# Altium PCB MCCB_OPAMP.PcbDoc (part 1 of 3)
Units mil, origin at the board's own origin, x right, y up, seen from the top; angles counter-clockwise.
Board outline 3937.01 x 3937.01 mil, 2 copper layers (Top Layer, Bottom Layer), stack 62 mil thick; 238 components, 115 nets, 518 pads, 159 vias.
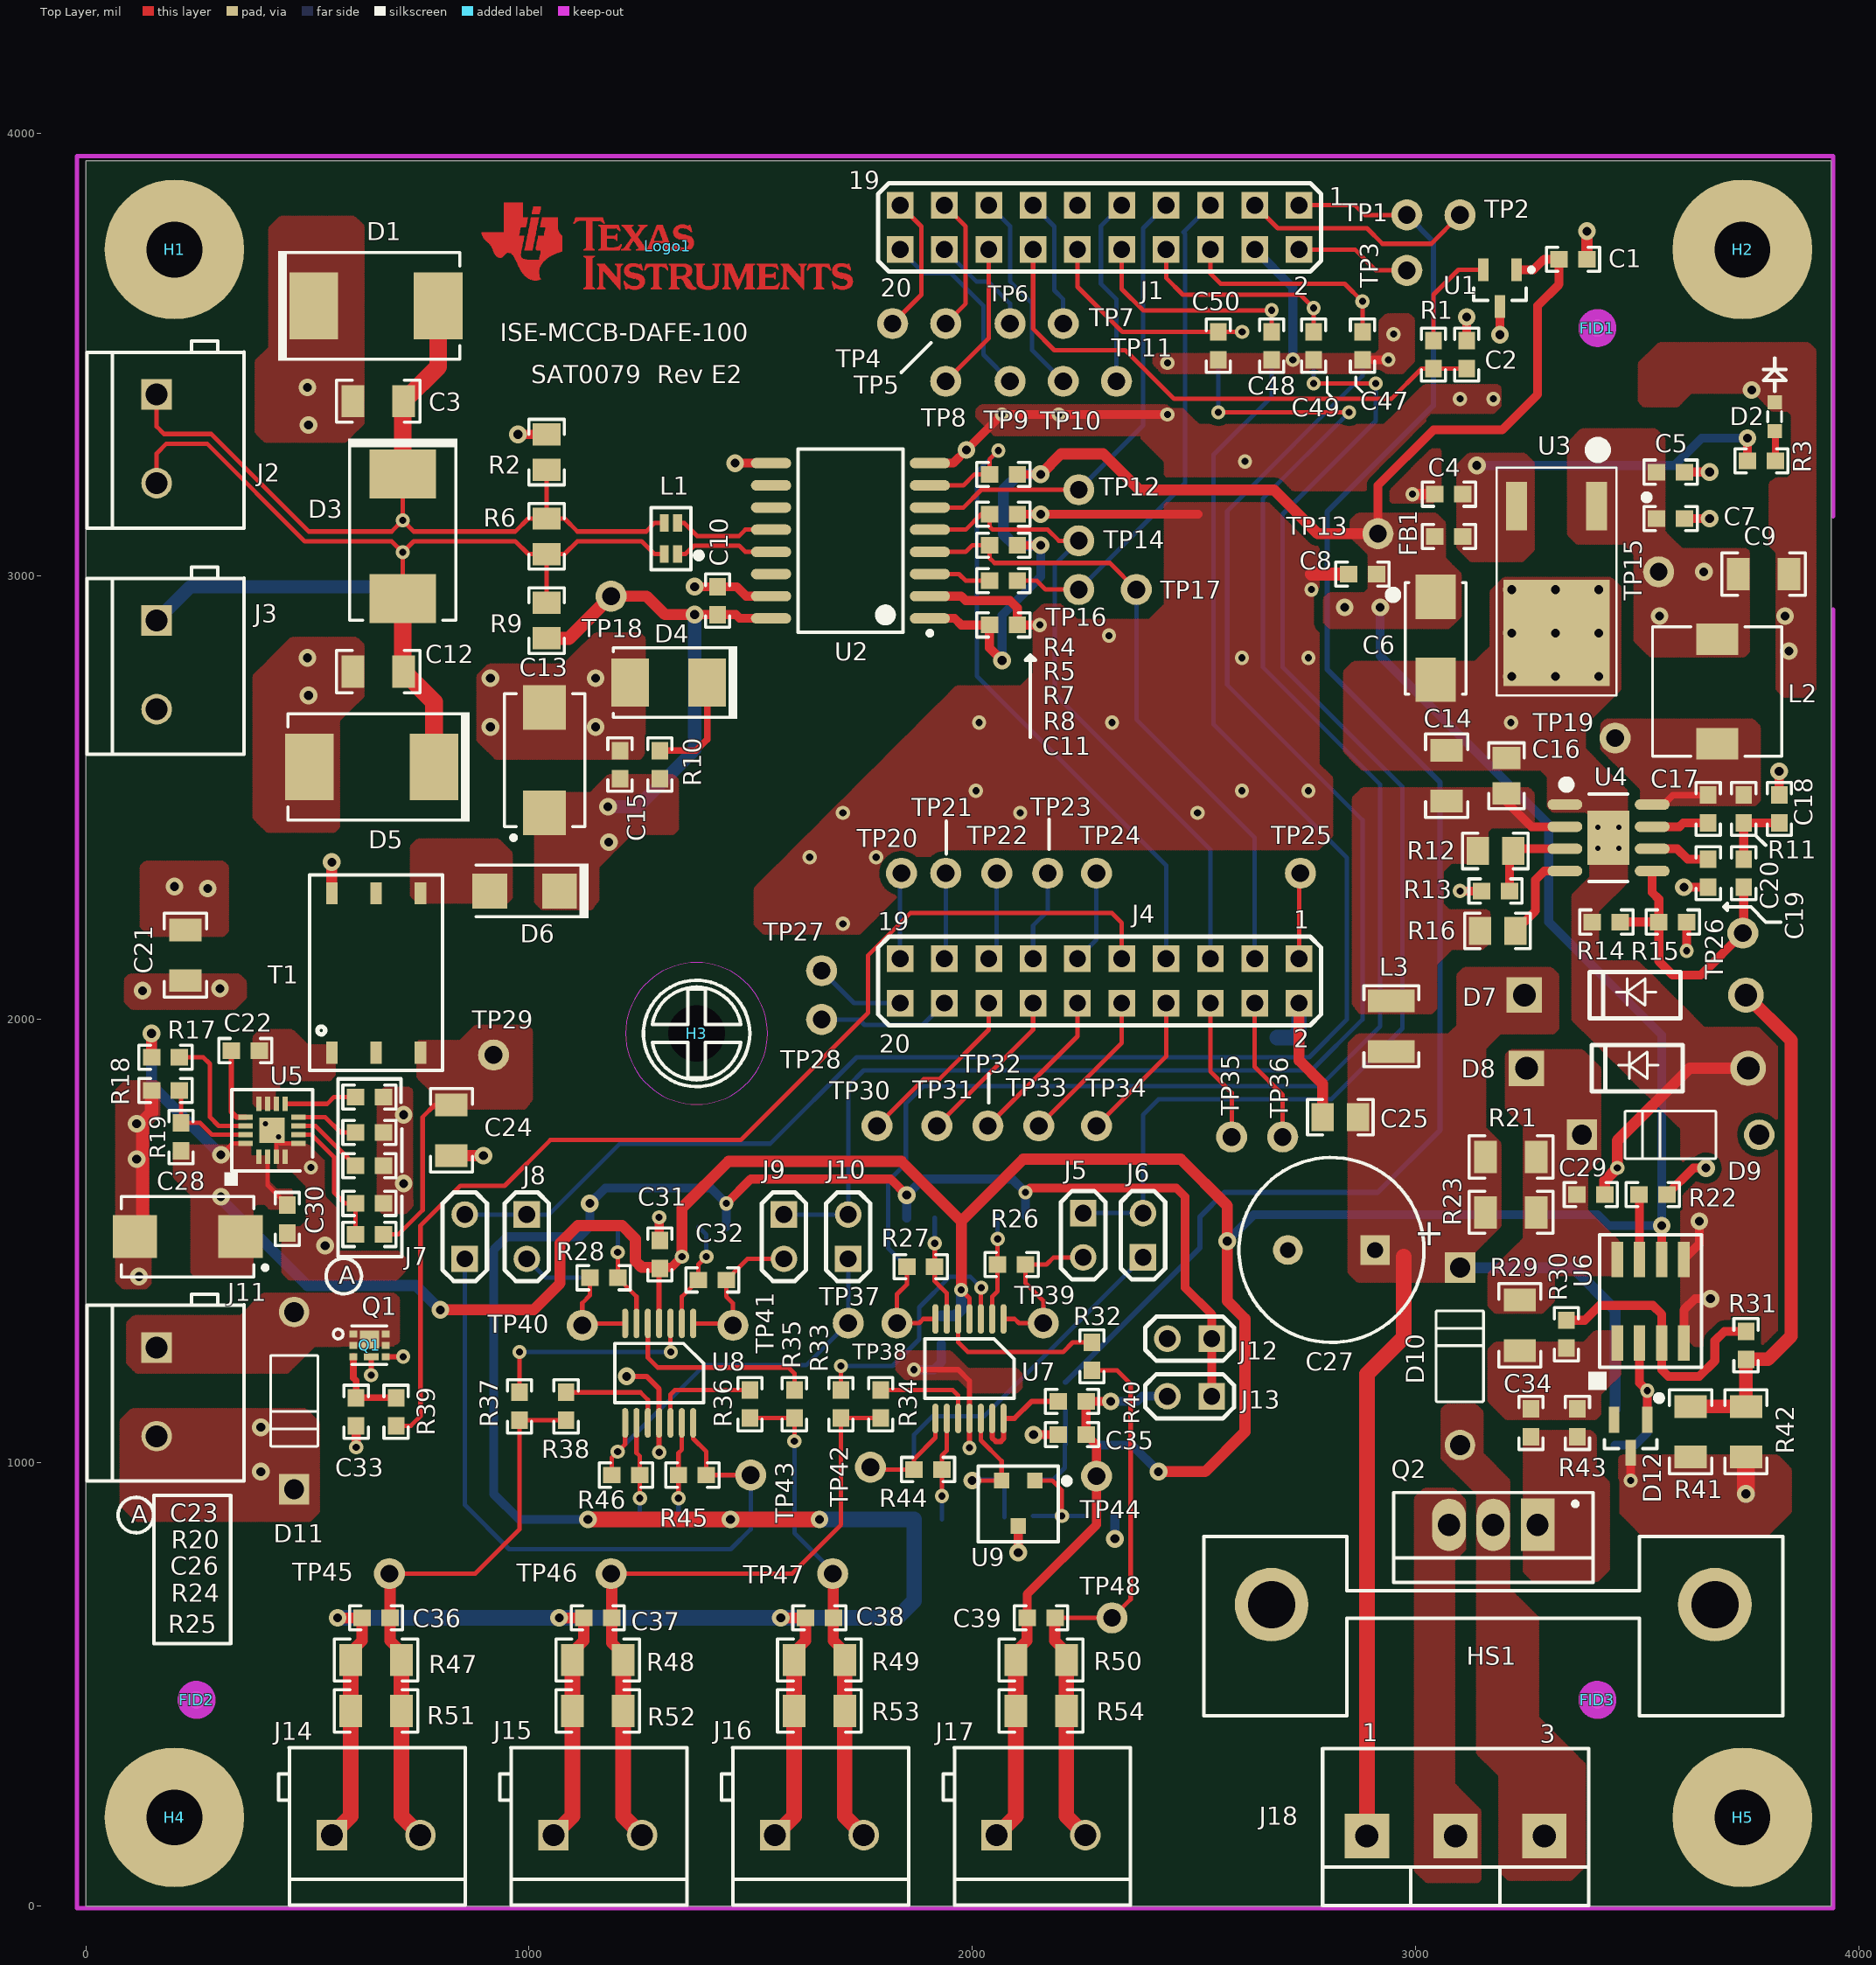
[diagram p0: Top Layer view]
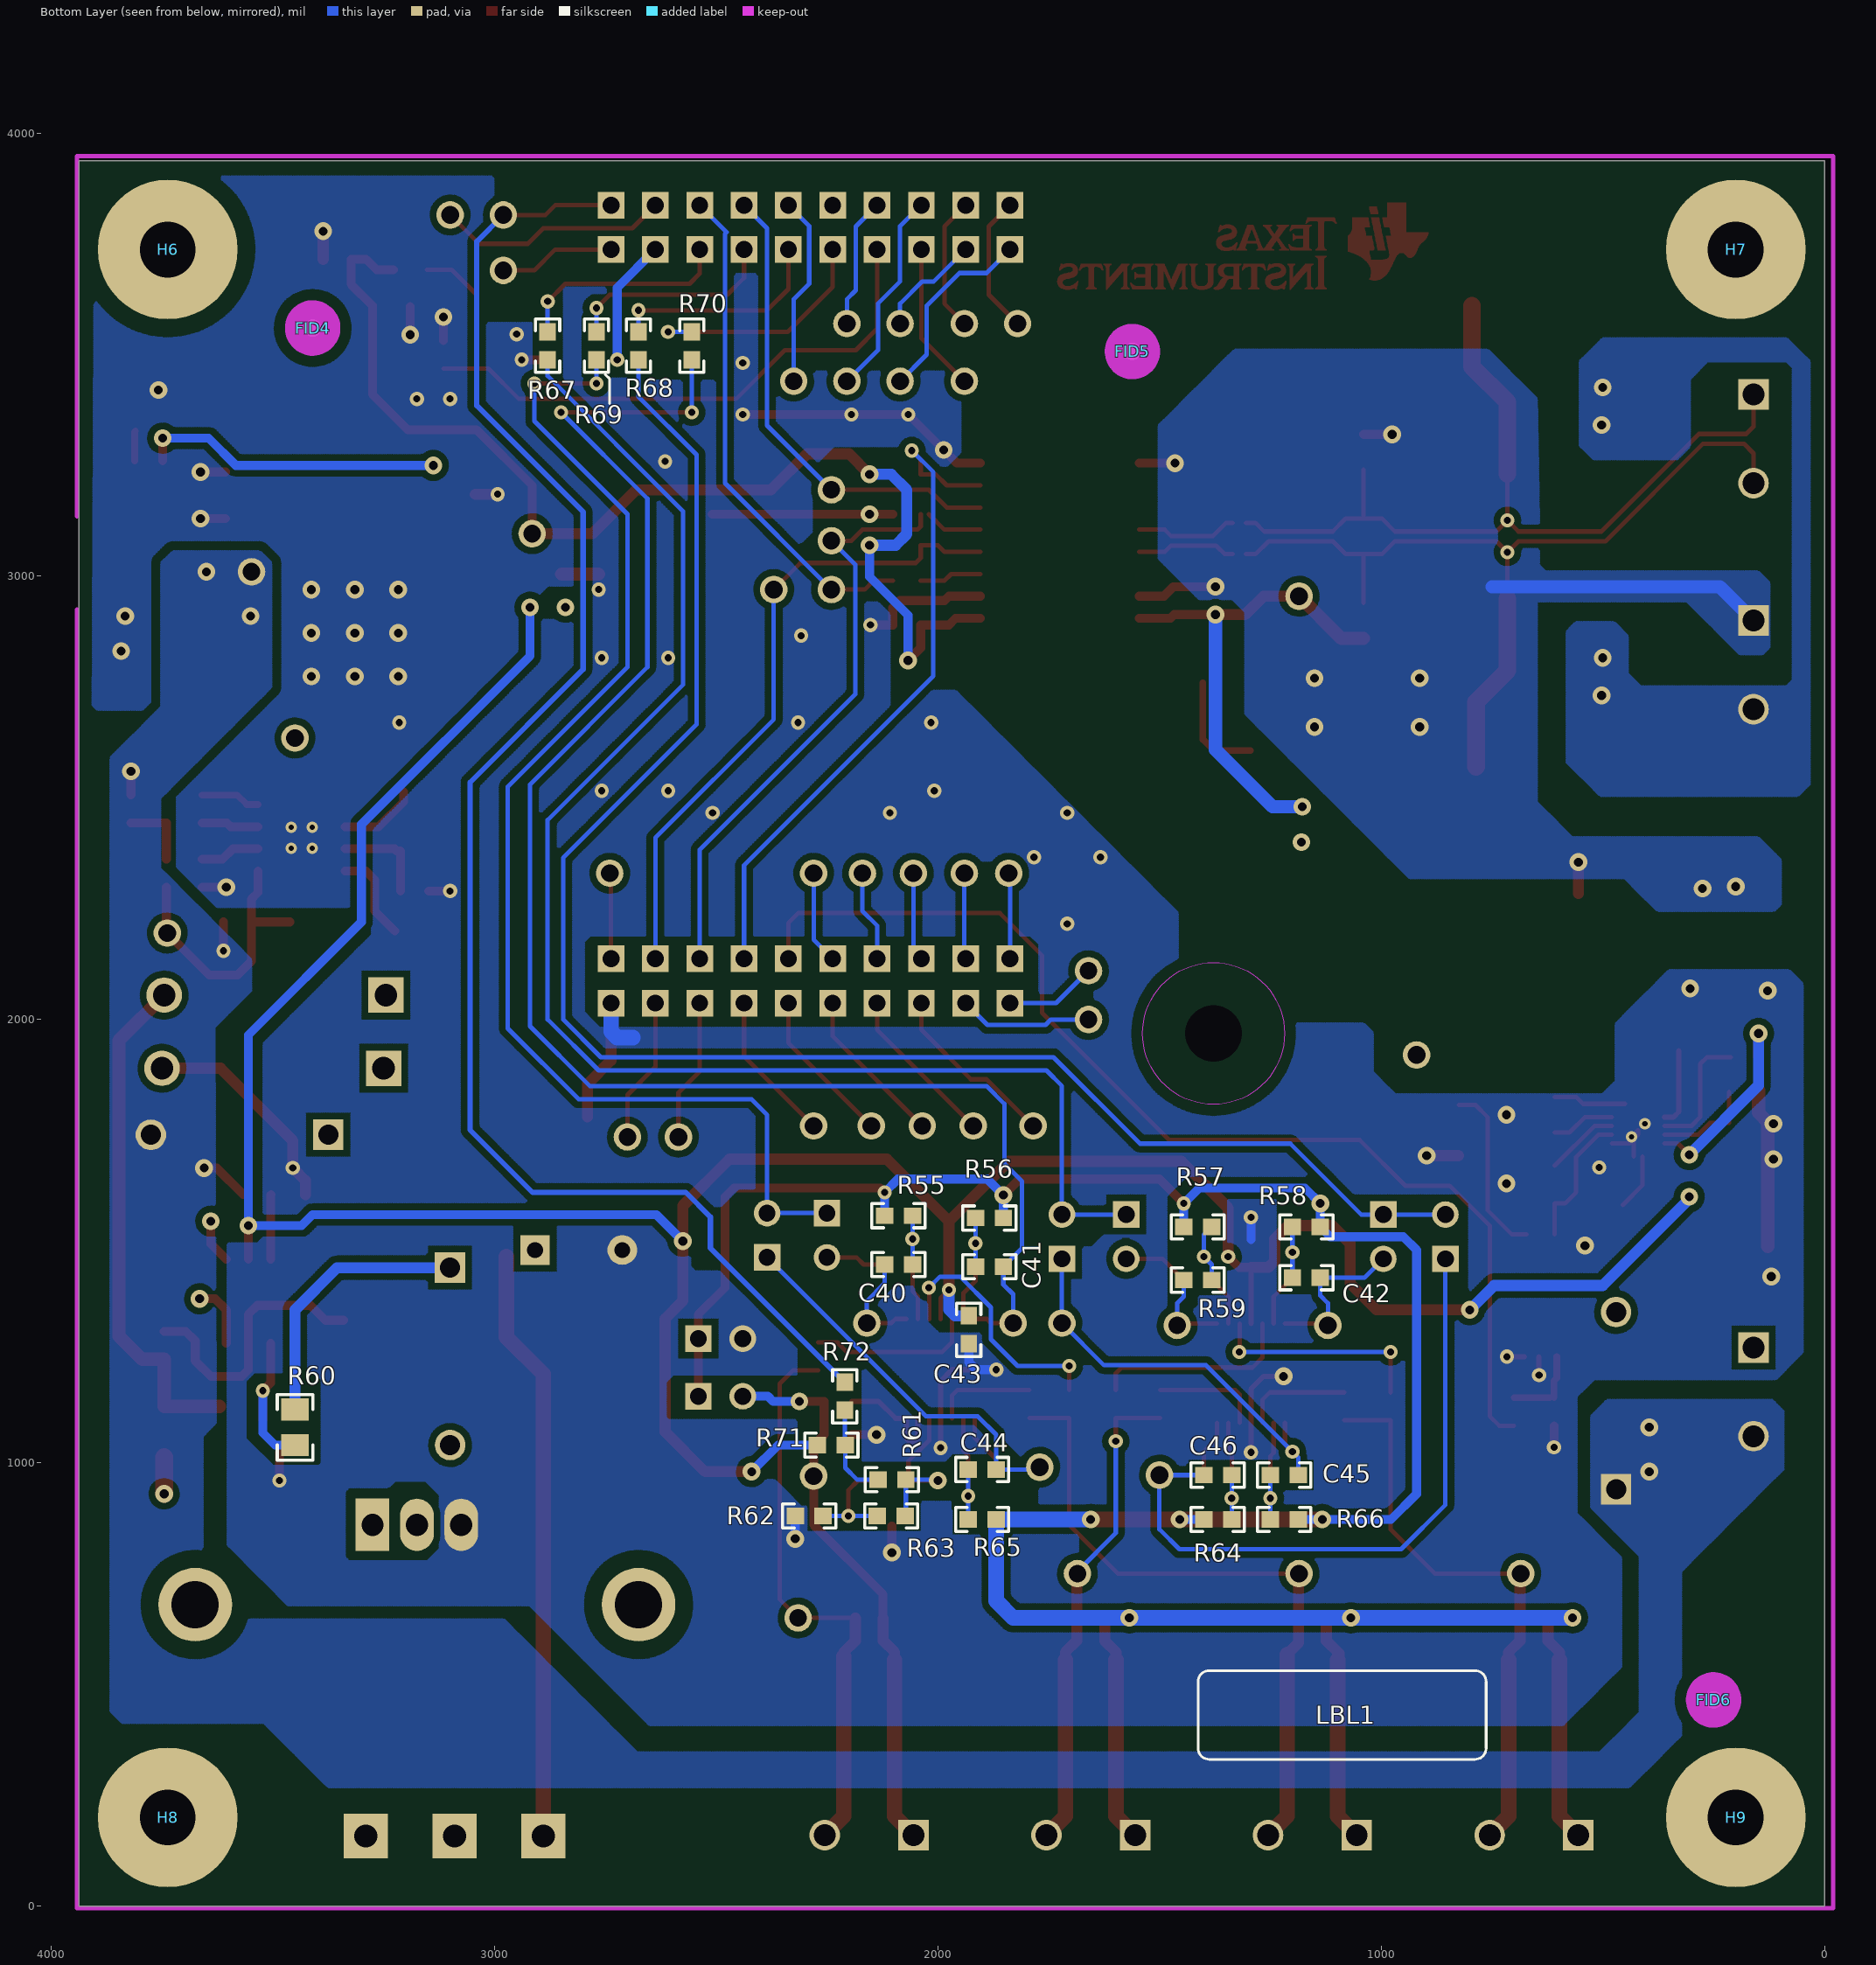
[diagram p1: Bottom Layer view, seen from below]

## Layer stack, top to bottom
Top Layer: signal copper 1.4
Dielectric: core 59.2, FR-4, Dk 4.8
Bottom Layer: signal copper 1.4

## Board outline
0,0 3937.01,0 3937.01,3937.01 0,3937.01

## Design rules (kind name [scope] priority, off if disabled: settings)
AcuteAngle [All] p1: minimum=4.50000000000000E+0001 checktracksonly=FALSE
AssemblyTestPointUsage [All] p1: valid=2
Clearance Clearance_MTG [InPadClass('MTG') vs InPolygon] p1: gap=40
Clearance Clearance_18V [InNet('18V')] p2: gap=22
Clearance Clearance_THPIN [IsVia vs IsThruPin] p3: gap=12
Clearance "Clearance_PAD Class" [InPadClass('U5') vs InPadClass('U5')] p4: gap=7.9
Clearance "Via to Via" [IsVia vs IsVia] p5: gap=12
Clearance "Via to SMT PIN" [IsVia vs IsSMTPin] p6: gap=12
Clearance "Clearance_Poly to Poly" [InPolygon vs InPolygon] p7: gap=20
Clearance Clearance_RS485 [InNetClass('RS485') vs InNetClass('RS485')] p8: gap=12
Clearance Clearance_BoardEdge_MountingHoles [OnCopper and InComponentClass('Mounting Holes') vs IsKeepOut] p9: gap=40
Clearance Clearance_BoardEdge_Poly [OnCopper and InPoly vs IsKeepOut] p10: gap=25
Clearance Clearance_BoardEdge [OnCopper and Not InComponentClass('Logo') and not InComponentClass('FiducialMark') and not InRegion(1000,500,4000,800) and Not IsKeepout vs IsKeepOut] p11: gap=75
Clearance Clearance_Poly [InPolygon] p12: gap=15
Clearance [All] p13: gap=8
ComponentClearance ComponentClearance_Logo [InComponentClass('Logo')] p1: gap=50 collisioncheckmode=3 verticalgap=10 showdistances=FALSE
ComponentClearance ComponentClearance_ScrewToNut [(HasFootprint('NY PMS 440 0025 PH')) vs (HasFootprint('Keystone_1902C'))] p2: gap=5 collisioncheckmode=3 verticalgap=10 showdistances=FALSE
ComponentClearance ComponentClearance_MountingHoles [InComponentClass('Mounting Holes')] p3: gap=250 collisioncheckmode=3 verticalgap=100000 showdistances=FALSE
ComponentClearance ComponentClearance_SmallPassives [HasFootprint('0201*') or HasFootprint('0402*') or HasFootprint('0508') or HasFootprint('0603*') or HasFootprint('0612') or HasFootprint('0805*') or HasFootprint('0815*') or HasFootprint('0830*') or HasFootprint('1206*') or HasFootprint('1210*') or HasFootprint('1808*') or HasFootprint('1812*') or HasFootprint('1825*') or HasFootprint('2010*') or HasFootprint('2220*') or HasFootprint('2225*') or HasFootprint('2512*') or HasFootprint('2728*') or HasFootprint('3518*') vs HasFootprint('0201*') or HasFootprint('0402*') or HasFootprint('0508') or HasFootprint('0603*') or HasFootprint('0612') or HasFootprint('0805*') or HasFootprint('0815*') or HasFootprint('0830*') or HasFootprint('1206*') or HasFootprint('1210*') or HasFootprint('1808*') or HasFootprint('1812*') or HasFootprint('1825*') or HasFootprint('2010*') or HasFootprint('2220*') or HasFootprint('2225*') or HasFootprint('2512*') or HasFootprint('2728*') or HasFootprint('3518*')] p4: gap=20 collisioncheckmode=3 verticalgap=10 showdistances=FALSE
ComponentClearance ComponentClearance_THtoSMT [IsThruComponent vs IsSMTComponent] p5: gap=100 collisioncheckmode=3 verticalgap=30 showdistances=FALSE
ComponentClearance ComponentClearance_THtoTH [IsThruComponent vs IsThruComponent] p6: gap=118.11 collisioncheckmode=3 verticalgap=30 showdistances=FALSE
ComponentClearance [All] p7: gap=40 collisioncheckmode=3 verticalgap=10 showdistances=FALSE
DiffPairsRouting DiffPair_RS485_2DiffPairsRouting [InDifferentialPair ('RS485_2')] p1: maxlimit=12 minlimit=12 mostfreqgap=12 maxuncoupledlength=500
DiffPairsRouting DiffPair_RS485_1DiffPairsRouting [InDifferentialPair ('RS485_1')] p2: maxlimit=12 minlimit=12 mostfreqgap=12 maxuncoupledlength=500
DiffPairsRouting [All] p3: maxlimit=100 minlimit=10 mostfreqgap=10 maxuncoupledlength=1000
FabricationTestPointUsage TestPointUsage [All] p1: valid=2 allowmultiple=FALSE
FabricationTestpoint Testpoint [All] p1: side=3 testpointundercomponent=TRUE minsize=40 maxsize=100 preferedsize=60 minholesize=0 maxholesize=40 preferedholesize=32 testpointgrid=1 allowsidetop=TRUE allowsidebottom=TRUE usegrid=TRUE gridtolerance=0.01
FanoutControl Fanout_LCC [IsLCC] p1: bgadir=Out bgaviamode=Centered fanoutstyle=Auto fanoutdirection=Alternating viagrid=1 // Fanout_LCC (Default Rule)
FanoutControl Fanout_BGA [IsBGA] p2: bgadir=Out bgaviamode=Centered fanoutstyle=Auto fanoutdirection=Alternating viagrid=1 // Fanout_BGA (Default Rule)
FanoutControl Fanout_Default [All] p4: bgadir=Out bgaviamode=Centered fanoutstyle=Auto fanoutdirection=Alternating viagrid=1 // Fanout_Default (Default Rule)
FanoutControl Fanout_Small [(CompPinCount < 5)] p5: bgadir=Out bgaviamode=Centered fanoutstyle=Auto fanoutdirection=OutThenIn viagrid=1 // Fanout_Small (Default Rule)
HoleSize [All] p1: absolutevalues=TRUE maxlimit=251 minlimit=8 maxpercent=80.000 minpercent=20.000
MatchedLengths DiffPair_RS485_2MatchedLengths [InDifferentialPair ('RS485_2')] p1: tolerance=1000 checknetsindiffpair=TRUE checkdiffpairvsdiffpair=TRUE checkothers=TRUE
MatchedLengths DiffPair_RS485_1MatchedLengths [InDifferentialPair ('RS485_1')] p2: tolerance=1000 checknetsindiffpair=TRUE checkdiffpairvsdiffpair=TRUE checkothers=TRUE
MinimumAnnularRing MinimumAnnularRing_ThermalPadVias [IsVia and InAnyComponent] p1: minimumring=5.91
MinimumAnnularRing [All] p2: minimumring=7
MinimumSolderMaskSliver MinimumSolderMaskSliver_Logo [InComponentClass('Logo') vs InComponentClass('Logo')] p1: minsoldermaskwidth=0.7
MinimumSolderMaskSliver [All] p2: minsoldermaskwidth=3.94
PlaneConnect [All] p1: planeconnectstyle=Relief reliefexpansion=10 reliefentries=4 reliefconductorwidth=10 reliefairgap=10
PolygonConnect PolygonConnect_All [All] p1: connectstyle=Direct reliefconductorwidth=10 reliefentries=4 polygonreliefangle="90 Angle" airgapwidth=10
RoutingVias ThermalPadVias [IsVia and InAnyComponent] p1: holewidth=7.87 width=19.68 viastyle="Through Hole" minholewidth=7.87 minwidth=19.68 maxholewidth=12 maxwidth=26
RoutingVias [All] p2: holewidth=16 width=32 viastyle="Through Hole" minholewidth=12 minwidth=26 maxholewidth=20 maxwidth=40
SMDToCorner [All] p1: distance=30000
SilkToSilkClearance [All] p1: silktosilkclearance=5
SilkscreenOverComponentPads [All] p1: minsilkscreentomaskgap=5
SolderMaskExpansion [All] p1: expansion=2
Width DiffPair_RS485_2Width [InDifferentialPair('RS485_2')] p1: maxlimit=100 minlimit=10 preferedwidth=10
Width DiffPair_RS485_1Width [InDifferentialPair('RS485_1')] p2: maxlimit=100 minlimit=10 preferedwidth=10
Width Width_RS485 [InNetClass('RS485')] p3: maxlimit=100 minlimit=10 preferedwidth=10
Width [All] p4: maxlimit=100 minlimit=6 preferedwidth=10 checkconnectedcopper=TRUE
14 further rules are at their usual default settings.

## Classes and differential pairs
pad class MTG: H1-1 H2-1 H3-1 H5-1 HS1-1 HS1-2
pad class U5: U5-1 U5-2 U5-3 U5-4 U5-5 U5-6 U5-7 U5-8 U5-9 U5-10 U5-11 U5-12 U5-13 U5-14 U5-15 U5-16
net class RS485: RS485_ISO_A RS485_ISO_B
net class PWR: 12V C5V EGND GND PGND UC3.3V VCC/2 VREF_PH
component class Label: LBL1
component class AssemblyNote: ZZ1 ZZ2 ZZ3 ZZ4
component class FiducialMark: FID1 FID2 FID3 FID4 FID5 FID6
component class "Pg7 Hardware": FID1 FID2 FID3 FID4 FID5 FID6 H1 H2 H3 H4 H5 H6 H7 H8 H9 LBL1 Logo1 ZZ1 ZZ2 ZZ3 ZZ4
component class Logo: Logo1
component class "Mounting Holes": H1 H2 H4 H5
component class Pg3: C4 C5 C6 C7 C8 C9 C14 C16 C17 C18 C19 C20 C25 C27 C29 C33 C34 D2 D7 D8 D9 D10 D11 D12 FB1 HS1 J11 J18 L2 L3 Q1 Q2 R3 R11 R12 R13 R14 R15 R16 R21 R22 R23 R29 R30 R31 R39 R41 R42 R43 R60 TP13 TP15 TP19 TP26 U3 U4 U6
component class Pg4: C1 C2 C31 C32 C35 C36 C37 C38 C39 C40 C41 C42 C43 C44 C45 C46 C47 C48 C49 C50 J5 J6 J7 J8 J9 J10 J12 J13 J14 J15 J16 J17 R1 R26 R27 R28 R32 R33 R34 R35 R36 R37 R38 R40 R44 R45 R46 R47 R48 R49 R50 R51 R52 R53 R54 R55 R56 R57 R58 R59 R61 R62 R63 R64 R65 R66 R67 R68 R69 R70 R71 R72 TP37 TP38 TP39 TP40 TP41 TP42 TP43 TP44 TP45 TP46 TP47 TP48 U1 U7 U8 U9
component class Pg5: C3 C10 C11 C12 C13 C15 C21 C22 C23 C24 C26 C28 C30 D1 D3 D4 D5 D6 J2 J3 L1 R2 R4 R5 R6 R7 R8 R9 R10 R17 R18 R19 R20 R24 R25 T1 TP12 TP14 TP16 TP17 TP18 TP29 U2 U5
component class Pg6: J1 J4 TP1 TP2 TP3 TP4 TP5 TP6 TP7 TP8 TP9 TP10 TP11 TP20 TP21 TP22 TP23 TP24 TP25 TP27 TP28 TP30 TP31 TP32 TP33 TP34 TP35 TP36
differential pair RS485_2: +NetL1_2 -NetL1_1
differential pair RS485_1: +RS485_ISO_A -RS485_ISO_B

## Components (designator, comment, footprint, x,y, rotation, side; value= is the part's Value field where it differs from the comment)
C1 "06033C104JAT2A" 0603 3355,3715 r0 top (schematic designator C46)
C2 "06033C104JAT2A" 0603 3115,3500 r270 top (schematic designator C19)
C3 "CC1206KKX7RCBB102" 1206 660,3395 r180 top (schematic designator C34)
C4 "C1608X7R1C105K" 0603 3075,3185 r180 top (schematic designator C13)
C5 "C0603C104K5RACTU" 0603 3575,3235 r0 top (schematic designator C15)
C6 "293D475X9035C2TE3" 6032-28 3045,2860 r270 top (schematic designator C11)
C7 "C1608X7R1C105K" 0603 3575,3130 r0 top (schematic designator C14)
C8 "C0603C104K5RACTU" 0603 2880,3005 r180 top (schematic designator C12)
C9 "GRM31CR61C226KE15L" 1206 3785,3005 r0 top (schematic designator C8)
C10 "06033C104JAT2A" 0603 1425,2945 r270 top (schematic designator C32)
C11 "06033C104JAT2A" 0603 2070,2890 r180 top (schematic designator C31)
C12 "CC1206KKX7RCBB102" 1206 660,2785 r0 top (schematic designator C33)
C13 "T495X476K035ATE300" 7343-43 1035,2585 r90 top (schematic designator C40)
C14 "GRM31CR72A105KA01L" 1206 3070,2550 r270 top (schematic designator C1)
C15 "06033C104JAT2A" 0603 1205,2575 r90 top (schematic designator C41)
C16 "C0805C104K1RACTU" 0805_HV 3205,2550 r270 top (schematic designator C2)
C17 "C1608C0G1E103J" 0603 3660,2475 r90 top (schematic designator C6)
C18 "C0603C332K5RACTU" 0603 3820,2475 r270 top (schematic designator C7)
C19 "C1608X5R1E105K080AC" 0603 3660,2330 r270 top (schematic designator C10)
C20 "06033C104JAT2A" 0603 3740,2330 r90 top (schematic designator C9)
C21 "CC1206KKX7RCBB102" 1206 225,2145 r270 top (schematic designator C38)
C22 "06033C104JAT2A" 0603 360,1930 r180 top (schematic designator C35)
C23 "06033C104JAT2A" 0603 640,1825 r180 top (schematic designator C39)
C24 "1206YD226MAT2A" 1206 825,1750 r270 top (schematic designator C43)
C25 "C0805C104K1RACTU" 0805_HV 2830,1780 r180 top (schematic designator C4)
C26 "C1608C0G1E103J" 0603 640,1670 r0 top (schematic designator C42)
C27 "100YXJ100M10X20" YXJ_1000x2000 2810,1480 r180 top (schematic designator C3)
C28 "T495X476K035ATE300" 7343-43 230,1510 r180 top (schematic designator C36)
C29 "C0603C104K5RACTU" 0603 3395,1605 r0 top (schematic designator C45)
C30 "06033C104JAT2A" 0603 455,1550 r270 top (schematic designator C37)
C31 "06033C104JAT2A" 0603 1295,1470 r270 top (schematic designator C21)
C32 "06033C101KAT2A" 0603 1413.54,1412.27 r0 top (schematic designator C17)
C33 "06033C104JAT2A" 0603 610,1115 r270 top (schematic designator C16)
C34 "06033C104JAT2A" 0603 3260,1090 r270 top (schematic designator C5)
C35 "06033C104JAT2A" 0603 2225,1063.29 r0 top (schematic designator C44)
C36 "06033C101KAT2A" 0603 655,650 r180 top (schematic designator C22)
C37 "06033C101KAT2A" 0603 1155,650 r180 top (schematic designator C25)
C38 "06033C101KAT2A" 0603 1655,650 r180 top (schematic designator C28)
C39 "06033C101KAT2A" 0603 2155,650 r180 top (schematic designator C29)
C40 "06033C101KAT2A" 0603 2088.54,1447.27 r0 bottom (schematic designator C26)
C41 "06033C101KAT2A" 0603 1883.54,1442.27 r180 bottom (schematic designator C27)
C42 "06033C101KAT2A" 0603 1168.54,1417.27 r180 bottom (schematic designator C18)
C43 "06033C104JAT2A" 0603 1930,1300 r90 bottom (schematic designator C20)
C44 "06033C101KAT2A" 0603 1900,985 r180 bottom (schematic designator C30)
C45 "06033C101KAT2A" 0603 1218.54,972.27 r180 bottom (schematic designator C23)
C46 "06033C101KAT2A" 0603 1368.54,972.27 r0 bottom (schematic designator C24)
C47 "C1608C0G1E103J" 0603 2880,3520 r90 top
C48 "C1608C0G1E103J" 0603 2675,3520 r90 top
C49 "C1608C0G1E103J" 0603 2770,3520 r90 top
C50 "C1608C0G1E103J" 0603 2555,3520 r90 top
D1 "SMCJ15CA" SMC 654.66,3610 r0 top (schematic designator D8)
D2 "LED_LG L29K-G2J1-24-Z" LED0603AA 3810,3360 r270 top (schematic designator D4)
D3 "SMCJ15CA" SMC 715,3090 r270 top (schematic designator D7)
D4 "SMBJ5338B-TP" SMB 1315,2760 r180 top (schematic designator D10)
D5 "SMCJ15CA" SMC 645,2570 r180 top (schematic designator D6)
D6 "B120-13-F" SMA 990,2290 r180 top (schematic designator D9)
D7 "1N4754A-TP" DO-41#1 3245,2055 r0 top (schematic designator D2)
D8 "1N4745A-TP" DO-41#1 3250,1890 r0 top (schematic designator D11)
D9 "1N4007" DO-41#2 3575,1740 r0 top (schematic designator D12)
D10 "SB1100FSCT-ND" DO-41#2 3100,1240 r270 top (schematic designator D1)
D11 "1N4007" DO-41#2 470,1140 r90 top (schematic designator D5)
D12 "BAS21-7-F" SOT-23#1 3485,1060 r270 top (schematic designator D3)
FB1 "1000 OHM" 0603 3075,3090 r180 top
FID1 "Fiducial" Fiducial10-20 3410,3560 r0 top (schematic designator FID2)
FID2 "Fiducial" Fiducial10-20 250,465 r0 top (schematic designator FID1)
FID3 "Fiducial" Fiducial10-20 3410,465 r0 top
FID4 "Fiducial" Fiducial10-30 3410,3560 r90 bottom (schematic designator FID6)
FID5 "Fiducial" Fiducial10-30 1561,3507 r90 bottom
FID6 "Fiducial" Fiducial10-30 250,465 r90 bottom (schematic designator FID4)
H1 "NY PMS 440 0025 PH" "NY PMS 440 0025 PH" 200,3737.01 r0 top locked
H2 "NY PMS 440 0025 PH" "NY PMS 440 0025 PH" 3737.01,3737.01 r0 top
H3 "MH 3.2MM" MH3.2_H5_W6_KO8_STARHEAD 1377.95,1968.5 r0 top locked (schematic designator H13)
H4 "NY PMS 440 0025 PH" "NY PMS 440 0025 PH" 200,200 r0 top locked (schematic designator H3)
H5 "NY PMS 440 0025 PH" "NY PMS 440 0025 PH" 3737.01,200 r0 top locked (schematic designator H4)
H6 "1902C" Keystone_1902C 3737.01,3737.01 r180 bottom
H7 "1902C" Keystone_1902C 200,3737.01 r180 bottom locked (schematic designator H5)
H8 "1902C" Keystone_1902C 3737.01,200 r180 bottom locked
H9 "1902C" Keystone_1902C 200,200 r180 bottom locked (schematic designator H7)
HS1 "HEATSINK_513102B02500G" HEATSINK_513201 3175,680 r180 top
J1 "HEADER_2X10" HEADER_2X10P 2737.01,3837.01 r180 top (schematic designator J18)
J2 "ED120/2DS" CONN_ED120-2DS 160,3310 r180 top (schematic designator J17)
J3 "ED120/2DS" CONN_ED120-2DS 160,2800 r180 top (schematic designator J16)
J4 "HEADER_2X10" HEADER_2X10P 2737.01,2137.01 r180 top (schematic designator J19)
J5 "JUMPER_2X100MIL" HDR100_1X2 2250,1563.29 r270 top (schematic designator J11)
J6 "JUMPER_2X100MIL" HDR100_1X2 2385,1463.29 r90 top (schematic designator J15)
J7 "JUMPER_2X100MIL" HDR100_1X2 855,1460 r90 top
J8 "JUMPER_2X100MIL" HDR100_1X2 995,1560 r270 top (schematic designator J5)
J9 "JUMPER_2X100MIL" HDR100_1X2 1575,1560 r270 top (schematic designator J4)
J10 "JUMPER_2X100MIL" HDR100_1X2 1720,1460 r90 top (schematic designator J6)
J11 "ED120/2DS" CONN_ED120-2DS 160,1160 r180 top (schematic designator J2)
J12 "JUMPER_2X100MIL" HDR100_1X2 2540,1280 r180 top (schematic designator J14)
J13 "JUMPER_2X100MIL" HDR100_1X2 2540,1150 r180 top
J14 "ED120/2DS" CONN_ED120-2DS 655,160 r270 top (schematic designator J3)
J15 "ED120/2DS" CONN_ED120-2DS 1155,160 r270 top (schematic designator J8)
J16 "ED120/2DS" CONN_ED120-2DS 1655,160 r270 top (schematic designator J9)
J17 "ED120/2DS" CONN_ED120-2DS 2155,160 r270 top (schematic designator J12)
J18 "TBLK_15A_3X5.1MM" TB_3X5.1MM 2890,158 r0 top (schematic designator J1)
L1 "ACM2012-900-2P-T002" IND_0805-4P 1320,3085 r90 top (schematic designator L3)
L2 "SRR7032-221M" SRR7045 3680,2740 r90 top
L3 "B82422H1332K" 1210 2945,1985 r90 top (schematic designator L1)
LBL1 "Size: 0.65\" x 0.20 \"" Label_650x200 1088,431 r180 bottom
Logo1 "Texas Instruments" TI_Stacked_SolderMask_Small 1312,3745 r0 top
Q1 "CSD17571Q2" SON_CSD17571Q2 640,1265 r270 top (schematic designator Q2)
Q2 "CSD18537NKCS" TO-220AB 3175,860 r180 top (schematic designator Q1)
R1 "CRCW0603100RFKEA" 0603 3040,3500 r270 top (schematic designator R14)
R2 "CRCW0805470RFKEA" 0805_HV 1040,3280 r270 top (schematic designator R52)
R3 "CRCW0603300RJNEA" 0603 3780,3260 r180 top (schematic designator R12)
R4 "CRCW060310K0JNEA" 0603 2070,3230 r0 top (schematic designator R48)
R5 "CRCW060310K0JNEA" 0603 2070,3140 r180 top (schematic designator R53)
R6 "CRCW0805120RJNEA" 0805_HV 1040,3090 r270 top (schematic designator R51)
R7 "CRCW060310K0JNEA" 0603 2070,3070 r0 top (schematic designator R49)
R8 "CRCW060310R0FKEA" 0603 2070,2990 r180 top (schematic designator R50)
R9 "CRCW0805470RFKEA" 0805_HV 1040,2900 r270 top (schematic designator R47)
R10 "CRCW0603200RFKEA" 0603 1295,2575 r270 top (schematic designator R57)
R11 "CRCW060363K4FKEA" 0603 3740,2475 r270 top (schematic designator R6)
R12 "RT0805BRD07121KL" 0805_HV 3180,2380 r180 top (schematic designator R7)
R13 "CRCW060310K0FKEA" 0603 3180,2290 r0 top (schematic designator R11)
R14 "RC0603FR-071KL" 0603 3430,2220 r0 top (schematic designator R10)
R15 "CRCW06039K76FKEA" 0603 3580,2220 r0 top (schematic designator R8)
R16 "RG2012P-5362-B-T5" 0805_HV 3185,2200 r180 top (schematic designator R3)
R17 "CRCW0603100KFKEA" 0603 180,1915 r180 top (schematic designator R54)
R18 "CRCW060321K5FKEA" 0603 180,1840 r0 top (schematic designator R56)
R19 "CRCW060330K0JNEA" 0603 215,1735 r270 top (schematic designator R55)
R20 "CRCW0603280KFKEA" 0603 640,1745 r180 top (schematic designator R60)
R21 "CRCW120610K0FKEA" 1206 3215,1690 r180 top (schematic designator R64)
R22 "CRCW060310K0FKEA" 0603 3535,1605 r0 top (schematic designator R62)
R23 "CRCW120610K0FKEA" 1206 3215,1565 r180 top (schematic designator R65)
R24 "CRCW060343K2FKEA" 0603 640,1585 r180 top (schematic designator R59)
R25 "CRCW0603100KFKEA" 0603 640,1515 r180 top (schematic designator R58)
R26 "CRCW060368K0JNEA" 0603 2088.54,1447.27 r0 top (schematic designator R33)
R27 "CRCW060368K0JNEA" 0603 1883.54,1442.27 r180 top (schematic designator R34)
R28 "CRCW060368K0JNEA" 0603 1168.54,1417.27 r180 top (schematic designator R16)
R29 "CRCW120610K0FKEA" 1206 3235,1310 r270 top (schematic designator R66)
R30 "CRCW06031M00FKEA" 0603 3340,1290 r270 top (schematic designator R1)
R31 "RNCF0603TKY10K0" 0603 3745,1265 r270 top (schematic designator R4)
R32 "RNCF0603TKY10K0" 0603 2270,1240 r90 top (schematic designator R38)
R33 "RNCF0603TKY10K0" 0603 1703.54,1132.27 r90 top (schematic designator R37)
R34 "RNCF0603TKY10K0" 0603 1793.54,1132.27 r90 top (schematic designator R44)
R35 "RNCF0603TKY10K0" 0603 1598.54,1132.27 r90 top (schematic designator R20)
R36 "RNCF0603TKY10K0" 0603 1498.54,1132.27 r90 top (schematic designator R30)
R37 "RNCF0603TKY10K0" 0603 978.54,1127.27 r90 top (schematic designator R19)
R38 "RNCF0603TKY10K0" 0603 1083.54,1127.27 r90 top (schematic designator R29)
R39 "CRCW0603300RJNEA" 0603 700,1115 r90 top (schematic designator R13)
R40 "CRCW0603100RFKEA" 0603 2225,1138.29 r0 top (schematic designator R61)
R41 "CRCW12061K00FKEA" 1206 3620,1070 r90 top (schematic designator R63)
R42 "CRCW12061K00FKEA" 1206 3745,1070 r90 top (schematic designator R9)
R43 "RG1608P-511-B-T5" 0603 3365,1090 r270 top (schematic designator R5)
R44 "RC0603JR-0727KL" 0603 1900,985 r180 top (schematic designator R41)
R45 "RC0603JR-0727KL" 0603 1368.54,972.27 r0 top (schematic designator R24)
R46 "RC0603JR-0727KL" 0603 1218.54,972.27 r180 top (schematic designator R23)
R47 "CRCW120622R0JNEA" 1206 655,555 r0 top (schematic designator R22)
R48 "CRCW120622R0JNEA" 1206 1155,555 r0 top (schematic designator R26)
R49 "CRCW120622R0JNEA" 1206 1655,555 r0 top (schematic designator R32)
R50 "CRCW120622R0JNEA" 1206 2155,555 r0 top (schematic designator R40)
R51 "CRCW120622R0JNEA" 1206 655,440 r0 top (schematic designator R21)
R52 "CRCW120622R0JNEA" 1206 1155,440 r0 top (schematic designator R25)
R53 "CRCW120622R0JNEA" 1206 1655,440 r0 top (schematic designator R31)
R54 "CRCW120622R0JNEA" 1206 2155,440 r0 top (schematic designator R39)
R55 "RNCF0603TKY10K0" 0603 2088.54,1557.27 r180 bottom (schematic designator R35)
R56 "RNCF0603TKY10K0" 0603 1883.54,1552.27 r0 bottom (schematic designator R36)
R57 "RNCF0603TKY10K0" 0603 1413.54,1532.27 r180 bottom (schematic designator R17)
R58 "RNCF0603TKY10K0" 0603 1168.54,1532.27 r0 bottom (schematic designator R18)
R59 "CRCW060368K0JNEA" 0603 1413.54,1412.27 r0 bottom (schematic designator R15)
R60 "ERJ-6GEYJ473V" 0805_HV 3450,1080 r90 bottom (schematic designator R2)
R61 "CRCW0603470RJNEA" 0603 2103.54,962.27 r0 bottom (schematic designator R42)
R62 "RNCF0603TKY10K0" 0603 2290,880 r180 bottom (schematic designator R46)
R63 "CRCW060330K0JNEA" 0603 2105,880 r180 bottom (schematic designator R45)
R64 "RNCF0603TKY10K0" 0603 1368.54,872.27 r180 bottom (schematic designator R28)
R65 "RNCF0603TKY10K0" 0603 1900,872.27 r0 bottom (schematic designator R43)
R66 "RNCF0603TKY10K0" 0603 1218.54,872.27 r0 bottom (schematic designator R27)
R67 "CRCW0603100RFKEA" 0603 2880,3520 r90 bottom
R68 "CRCW0603100RFKEA" 0603 2675,3520 r90 bottom
R69 "CRCW0603100RFKEA" 0603 2770,3520 r90 bottom
R70 "CRCW0603100RFKEA" 0603 2555,3520 r90 bottom
R71 "CRCW0603100RFKEA" 0603 2240,1040 r180 bottom
R72 "CRCW06030000Z0EA" 0603 2210,1150 r270 bottom
T1 "760390015" 760390015 555,1925 r90 top
TP1 "TP-040_RND" TP-040_RND 2980,3815 r90 top (schematic designator TP23)
TP2 "TP-040_RND" TP-040_RND 3100,3815 r90 top (schematic designator TP41)
TP3 "TP-040_RND" TP-040_RND 2980,3690 r90 top (schematic designator TP25)
TP4 "TP-040_RND" TP-040_RND 1820,3570 r90 top (schematic designator TP40)
TP5 "TP-040_RND" TP-040_RND 1940,3570 r90 top (schematic designator TP39)
TP6 "TP-040_RND" TP-040_RND 2085,3570 r90 top (schematic designator TP36)
TP7 "TP-040_RND" TP-040_RND 2205,3570 r90 top (schematic designator TP33)
TP8 "TP-040_RND" TP-040_RND 1940,3440 r90 top (schematic designator TP42)
TP9 "TP-040_RND" TP-040_RND 2085,3440 r90 top (schematic designator TP38)
TP10 "TP-040_RND" TP-040_RND 2205,3440 r90 top (schematic designator TP34)
TP11 "TP-040_RND" TP-040_RND 2325,3440 r90 top (schematic designator TP29)
TP12 "TP-040_RND" TP-040_RND 2240,3195 r90 top (schematic designator TP20)
TP13 "TP-040_RND" TP-040_RND 2915,3096 r0 top (schematic designator TP4)
TP14 "TP-040_RND" TP-040_RND 2240,3080 r90 top (schematic designator TP19)
TP15 "TP-040_RND" TP-040_RND 3548,3010 r0 top (schematic designator TP2)
TP16 "TP-040_RND" TP-040_RND 2240,2970 r90 top (schematic designator TP17)
TP17 "TP-040_RND" TP-040_RND 2370,2970 r90 top (schematic designator TP18)
TP18 "TP-040_RND" TP-040_RND 1185,2955 r90 top (schematic designator TP21)
TP19 "TP-040_RND" TP-040_RND 3450,2635 r0 top (schematic designator TP1)
TP20 "TP-040_RND" TP-040_RND 1840,2330 r90 top (schematic designator TP37)
TP21 "TP-040_RND" TP-040_RND 1940,2330 r90 top (schematic designator TP35)
TP22 "TP-040_RND" TP-040_RND 2055,2330 r90 top (schematic designator TP45)
TP23 "TP-040_RND" TP-040_RND 2170,2330 r90 top (schematic designator TP43)
TP24 "TP-040_RND" TP-040_RND 2280,2330 r90 top (schematic designator TP31)
TP25 "TP-040_RND" TP-040_RND 2740,2330 r90 top (schematic designator TP24)
TP26 "TP-040_RND" TP-040_RND 3738,2195 r0 top (schematic designator TP3)
TP27 "TP-040_RND" TP-040_RND 1660,2110 r90 top (schematic designator TP48)
TP28 "TP-040_RND" TP-040_RND 1660,2000 r90 top (schematic designator TP47)
TP29 "TP-040_RND" TP-040_RND 920,1920 r90 top (schematic designator TP22)
TP30 "TP-040_RND" TP-040_RND 1785,1760 r90 top (schematic designator TP46)
TP31 "TP-040_RND" TP-040_RND 1920,1760 r90 top (schematic designator TP44)
TP32 "TP-040_RND" TP-040_RND 2035,1760 r90 top
TP33 "TP-040_RND" TP-040_RND 2150,1760 r90 top (schematic designator TP30)
TP34 "TP-040_RND" TP-040_RND 2280,1760 r90 top (schematic designator TP28)
TP35 "TP-040_RND" TP-040_RND 2585,1735 r90 top (schematic designator TP27)
TP36 "TP-040_RND" TP-040_RND 2700,1735 r90 top (schematic designator TP26)
TP37 "TP-040_RND" TP-040_RND 1720,1315 r90 top (schematic designator TP10)
TP38 "TP-040_RND" TP-040_RND 1830,1315 r90 top (schematic designator TP13)
TP39 "TP-040_RND" TP-040_RND 2160,1315 r90 top (schematic designator TP12)
TP40 "TP-040_RND" TP-040_RND 1120,1310 r0 top (schematic designator TP5)
TP41 "TP-040_RND" TP-040_RND 1460,1310 r0 top (schematic designator TP7)
TP42 "TP-040_RND" TP-040_RND 1770,990 r90 top (schematic designator TP15)
TP43 "TP-040_RND" TP-040_RND 1500,972.27 r0 top (schematic designator TP9)
TP44 "TP-040_RND" TP-040_RND 2280,970 r90 top (schematic designator TP16)
TP45 "TP-040_RND" TP-040_RND 685,750 r0 top (schematic designator TP6)
TP46 "TP-040_RND" TP-040_RND 1185,750 r0 top (schematic designator TP8)
TP47 "TP-040_RND" TP-040_RND 1685,750 r90 top (schematic designator TP11)
TP48 "TP-040_RND" TP-040_RND 2315,650 r90 top (schematic designator TP14)
U1 "LM62BIM3" MF03A_N 3190,3650 r270 top (schematic designator U4)
U2 "ISO1176DW" DW0016A_N 1725,3080 r180 top (schematic designator U8)
U3 "TPS7A6533QKVURQ1" KVU_1 3318,3015 r180 top
U4 "LM5017MRE/NOPB" DDA0008B_N 3435,2410 r0 top (schematic designator U1)
U5 "TPS55010RTE" RTE-16 420.05,1750.15 r90 top (schematic designator U9)
U6 "LM293AD" SO8 3530,1365 r90 top (schematic designator U2)
U7 "OPA4314AIPW" PW0014A_N 1993.54,1212.27 r270 top (schematic designator U6)
U8 "OPA4314AIPW" PW0014A_N 1293.55,1202.26 r270 top (schematic designator U5)
U9 "LM4041BIDBZ" SOT-23#2 2103.54,907.27 r180 top (schematic designator U7)
ZZ1 "This Assembly Note is for PCB labels only" AssemblyNoteLabel 275,4700 r0 top
ZZ2 "These assemblies are ESD sensitive, ESD precautions shall be observed." AssemblyNote 270,4605 r0 top
ZZ3 "These assemblies must be clean and free from flux and all contaminants. Use of no clean flux is not acceptable." AssemblyNote 265,4500 r0 top
ZZ4 "These assemblies must comply with workmanship standards IPC-A-610 Class 2, unless otherwise specified." AssemblyNote 265,4395 r0 top

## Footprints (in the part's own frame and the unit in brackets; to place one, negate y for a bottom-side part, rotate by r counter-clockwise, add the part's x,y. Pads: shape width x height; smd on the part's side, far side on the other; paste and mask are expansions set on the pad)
0603 [mm] "0603 from SM-752 data"
  rect 1x0.95 smd: 1(-0.8,0) 2(0.8,0)
  silkscreen extent -1.52,-0.69 1.52,0.69, body extent -0.87,-0.47 0.87,0.47, height 0.85
0805_HV [mil] "0805 with 30mil clearance between pads"
  rect 50x63 smd: 1(-40,0) 2(40,0)
  silkscreen extent -74,-40 74,40, body extent -43,-29 43,29, height 43
1206 [mm] "1206 from SM-752 data"
  rect 1.3x1.85 smd: 1(-1.45,0) 2(1.45,0)
  silkscreen extent -2.4,-1.21 2.4,1.21, body extent -1.7,-0.9 1.7,0.9, height 1.35
1210 [mm] "1210 from SM-752 data"
  rect 1.3x2.7 smd: 1(-1.45,0) 2(1.45,0)
  silkscreen extent -2.32,-1.57 2.32,1.57, body extent -1.7,-1.35 1.7,1.35, height 1.35
6032-28 [mm] "Medium Density IPC based on Vishay Sprague 293D datasheet."
  rect 2.55x2.3 smd: 1(-2.375,0) 2(2.375,0)
  silkscreen extent -3.2,-2.59 3.2,1.75, body extent -3.15,-1.75 3.15,1.75, height 2.8
7343-43 [mm] "Medium density IPC based on Kemet T495 series"
  rect 2.55x2.45 smd: 1(-3.025,0) 2(3.025,0)
  silkscreen extent -4.56,-2.3 3.8,2.3, body extent -3.8,-2.3 3.8,2.3, height 4.3
760390015 [mm]
  rect 1.27x0.66 smd: 1(0,0) 2(0,-2.54) 3(0,-5.08) 4(9.14,-5.08) 5(9.14,-2.54) 6(9.14,0)
  silkscreen extent -1,-6.35 10.2,1.27, body extent -1,-6.4 10.2,1.2, height 4.2
AssemblyNote [mil] "Assembly Note"
AssemblyNoteLabel [mil] "Assembly Note for PCB Labels"
CONN_ED120-2DS [mm] "ONSHORE"
  rect 1.75x1.75 hole 1.25: 1(0,-2.54)
  round 1.75 hole 1.25: 2(0,2.54)
  silkscreen extent -5,-5.6 4,5.12, body extent -5,-5.6 4.15,5.12, height 13.1
DDA0008B_N [mm] "SOIC, 8-Leads, Body 4.9x3.9mm, Pitch 1.27mm, Exposed Pad, IPC Medium Density"
  oval 2x0.6 smd: 1(-2.5,1.905) 2(-2.5,0.635) 3(-2.5,-0.635) 4(-2.5,-1.905) 5(2.5,-1.905) 6(2.5,-0.635) 7(2.5,0.635) 8(2.5,1.905)
  rect 2.41x3.1 smd: 9(0,0)
  silkscreen extent -2.56,-2.5 1.1,3.2, body extent -2,-2.5 2,2.5, height 1.68
DO-41#1 [mil]
  rect 80x80 hole 51: 1(0,0)
  round 80 hole 51: 2(500,0)
  silkscreen extent 148,-52 352,52
DO-41#2 [mil] "diode"
  rect 68.9x68.9 hole 45.28: 1(-200,0)
  round 68.9 hole 45.28: 2(200,0)
  silkscreen extent -103,-54 102,53, body extent -217,-54 217,54, height 107
DW0016A_N [mm] "SOIC, 16-Leads, Body 10.3x7.5mm, Pitch 1.27mm, IPC Medium Density"
  oval 2.3x0.6 smd: 1(-4.55,4.445) 2(-4.55,3.175) 3(-4.55,1.905) 4(-4.55,0.635) 5(-4.55,-0.635) 6(-4.55,-1.905) 7(-4.55,-3.175) 8(-4.55,-4.445) 9(4.55,-4.445) 10(4.55,-3.175) 11(4.55,-1.905) 12(4.55,-0.635) 13(4.55,0.635) 14(4.55,1.905) 15(4.55,3.175) 16(4.55,4.445)
  silkscreen extent -4.67,-5.25 3,5.42, body extent -3.79,-5.25 3.8,5.25, height 2.64
Fiducial10-20 [mm]
  round 1 smd mask+0.5: 1(0,0)
  Top Layer keep-out circle w1.178: c0,0 r0.5
Fiducial10-30 [mm]
  round 1 smd mask+1: 1(0,0)
  Top Layer keep-out circle w1.678: c0,0 r0.75
HDR100_1X2 [mil]
  rect 60x60 hole 38: 1(0,0)
  round 60 hole 38: 2(100,0)
  silkscreen extent -50,-50 150,50
HEADER_2X10P [mil]
  rect 60x60 hole 38: 1(0,0) 2(0,100) 3(100,0) 4(100,100) 5(200,0) 6(200,100) 7(300,0) 8(300,100) 9(400,0) 10(400,100) 11(500,0) 12(500,100) 13(600,0) 14(600,100) 15(700,0) 16(700,100) 17(800,0) 18(800,100) 19(900,0) 20(900,100)
  silkscreen extent -50,-50 950,150
HEATSINK_513201 [mil]
  round 166 hole 106.5: 1(-500,0) 2(500,0)
IND_0805-4P [mil]
  rect 40x20 smd: 1(-35,-15) 2(35,-15) 3(35,15) 4(-35,15)
Keystone_1902C [mil] "Hex Standoff, 4-40 threaded, nylon"
  body extent -145,-126 146,126, height 501
KVU_1 [mm]
  rect 1.2x2.8 smd: 1(-2.29,-3.635) 3(2.29,-3.635)
  rect 6.096x6.096 smd: 2(0,3.635)
  silkscreen extent -3.43,-7.16 3.43,7.22
Label_650x200 [mil] "Thermal Transfer Label"
  silkscreen extent -325,-100 325,100, body extent -326,-101 326,101, height 1
LED0603AA [mil]
  rect 32x32 smd: 1(-32.48,0) 2(32.48,0)
  silkscreen extent -132,-25 11,25
MF03A_N [mm] "SOT23, 3-Leads, Body 2.9x1.3mm, Pitch 0.95mm, Lead Span 2.4mm, IPC Medium Density"
  rect 1.3x0.6 smd: 1(-1.05,0.95) 2(-1.05,-0.95) 3(1.05,0)
  silkscreen extent -1.17,-1.5 0.7,1.93, body extent -0.7,-1.5 0.7,1.5, height 1.12
MH3.2_H5_W6_KO8_STARHEAD [mil]
  round 20 / inner round 142 / far side round 20 hole 128 unplated mask+64: 1(0,0)
  Keep-Out Layer region: 160,0 147.82,61.23 113.14,113.14 61.23,147.82 0,160 0,160 -61.23,147.82 -113.14,113.14 -147.82,61.23 -160,0 -160,0 -147.82,-61.23 -113.14,-113.14 -61.23,-147.82 0,-160 0,-160 61.23,-147.82 113.14,-113.14 147.82,-61.23 160,0
  silkscreen extent -120,-120 120,120
"NY PMS 440 0025 PH" [mm] "4-40 nylon screw and mounting hole"
  round 8 hole 3.2: 1(0,0)
  body extent -3.3,-3.3 3.3,3.3, height 2.69
PW0014A_N [mm] "TSOP, 14-Leads, Body 5x4.4mm, Pitch 0.65mm, IPC Medium Density"
  oval 1.7x0.35 smd: 1(-2.85,1.95) 2(-2.85,1.3) 3(-2.85,0.65) 4(-2.85,0) 5(-2.85,-0.65) 6(-2.85,-1.3) 7(-2.85,-1.95) 8(2.85,-1.95) 9(2.85,-1.3) 10(2.85,-0.65) 11(2.85,0) 12(2.85,0.65) 13(2.85,1.3) 14(2.85,1.95)
  silkscreen extent -1.7,-2.55 1.7,2.55, body extent -3.21,-2.5 3.21,2.5, height 0.98
RTE-16 [mil]
  rect 32.24x11.8 smd: 1(-59.45,29.55) 2(-59.45,9.85) 3(-59.45,-9.85) 4(-59.45,-29.55) 9(59.55,-29.55) 10(59.55,-9.85) 11(59.55,9.85) 12(59.55,29.55)
  rect 11.8x32.24 smd: 5(-29.5,-59.5) 6(-9.8,-59.5) 7(9.9,-59.5) 8(29.6,-59.5) 14(9.9,59.5) 15(-9.8,59.5) 16(-29.5,59.5)
  rect 11.8x32.24 smd mask+2: 13(29.6,59.5)
  rect 57.09x57.09 smd: 17(0.15,-0.05)
  silkscreen extent -125,77 -95,107
SMA [mm] "Molded Diode, 2-Leads, Body 4.3x2.6mm, IPC Medium Density, based on OnSemi component dimensions and land pattern"
  rect 2x2 smd: 1(-2,0) 2(2,0)
  silkscreen extent -3.66,-1.57 2.79,1.57, body extent -2.6,-1.3 2.6,1.3, height 2.42
SMB [mil] "Molded Diode, 2-Leads, Body 5.4x3.6mm, IPC Medium Density, based on OnSemi component dimensions"
  rect 85x107.99 smd: 1(-87.01,0) 2(87.01,0)
  silkscreen extent -155,-82 125,82, body extent -106,-71 106,71, height 91
SMC [mil] "Molded Diode, 2-Leads, Body 6.9x5.8mm, IPC Medium Density, based on OnSemi component dimensions and land patterns"
  rect 110x150 smd: 1(-140.49,0) 2(140.49,0)
  silkscreen extent -221,-124 189,124, body extent -156,-116 156,116, height 91
SO8 [mil]
  rect 80x26 smd: 1(-95,75) 2(-95,25) 3(-95,-25) 4(-95,-75) 5(94,-75) 6(94,-25) 7(94,25) 8(94,75)
  silkscreen extent -200,100 -160,140
SON_CSD17571Q2 [mm] "SON, MOSFET, N-CH, 30V, 22A, SON 2X2 MM"
  rect 0.4x0.455 smd mask+0.038: 1(-0.65,-0.923) 2(0,-0.923) 5(0,0.923) 6(-0.65,0.923)
  rect 0.4x0.455 smd: 3(0.65,-0.923) 4(0.65,0.923)
  rect 0.4x0.85 smd mask+0.038: 7(0.65,0.096)
  rect 1.05x1.1 smd mask+0.038: 8(-0.325,0)
  silkscreen extent -1.1,-2.07 1.1,1, body extent -1,-1 1,0.97, height 0.85
SOT-23#1 [mm] "SOT23, 3-Leads, Body 2.9x1.3mm, Pitch 0.95mm, Lead Span 2.5mm, IPC Medium Density"
  rect 1.5x0.6 smd: 1(-0.95,0.95) 2(-0.95,-0.95) 3(0.95,0)
  silkscreen extent 0.2,-1.5 0.7,1.5, body extent -1.16,-1.45 1.21,1.45, height 1
SOT-23#2 [mm]
  rect 0.889x0.889 smd: 1(-0.952,-1.334) 2(0.953,-1.333) 3(0,1.27)
SRR7045 [mm] "BOURNS"
  rect 1.8x2.4 smd: 1(-3,0) 2(3,0)
  silkscreen extent -3.7,-3.7 3.7,3.7, body extent -3.65,-3.65 3.65,3.65, height 4.8
TB_3X5.1MM [mil]
  rect 100x100 hole 52: 1(0,0) 2(200,0) 3(400,0)
TI_Stacked_SolderMask_Small [mil]
  rect 850x200 on Top Solder paste-125 mask-125: 0(0,0)
  Top Layer region: 364.59,-40.71 365.32,-40.71 365.32,-42.89 366.04,-42.89 366.04,-45.07 366.77,-45.07 366.77,-47.26 367.5,-47.26 367.5,-50.16 368.23,-50.16 368.23,-52.34 368.95,-52.34 368.95,-55.25 366.77,-55.25 366.77,-53.8 366.04,-53.8 366.04,-53.07 365.32,-53.07 365.32,-52.34 364.59,-52.34 364.59,-51.62 363.86,-51.62 363.86,-50.89 363.14,-50.89 363.14,-50.16 362.41,-50.16 362.41,-49.44 361.68,-49.44 361.68,-48.71 360.96,-48.71 360.96,-47.98 358.77,-47.98 358.77,-47.26 355.87,-47.26 355.87,-46.53 349.32,-46.53 349.32,-47.26 348.6,-47.26 348.6,-47.98 347.87,-47.98 347.87,-91.6 348.6,-91.6 348.6,-93.06 349.32,-93.06 349.32,-93.78 350.78,-93.78 350.78,-94.51 352.96,-94.51 352.96,-95.24 353.69,-95.24 353.69,-97.42 329.69,-97.42 329.69,-95.24 330.42,-95.24 330.42,-94.51 332.6,-94.51 332.6,-93.78 334.06,-93.78 334.06,-93.06 334.78,-93.06 334.78,-91.6 335.51,-91.6 335.51,-47.98 334.78,-47.98 334.78,-47.26 334.06,-47.26 334.06,-46.53 327.51,-46.53 327.51,-47.26 324.61,-47.26 324.61,-47.98 323.15,-47.98 323.15,-48.71 321.7,-48.71 321.7,-49.44 320.97,-49.44 320.97,-50.16 320.24,-50.16 320.24,-50.89 319.52,-50.89 319.52,-51.62 318.79,-51.62 318.79,-53.07 318.06,-53.07 318.06,-53.8 317.34,-53.8 317.34,-54.52 316.61,-54.52 316.61,-55.25 315.15,-55.25 315.15,-54.52 314.43,-54.52 314.43,-53.8 315.15,-53.8 315.15,-51.62 315.88,-51.62 315.88,-48.71 316.61,-48.71 316.61,-46.53 317.34,-46.53 317.34,-44.35 318.06,-44.35 318.06,-42.17 318.79,-42.17 318.79,-39.98 364.59,-39.98
  Top Layer region: -163.21,-23.99 -163.94,-23.99 -163.94,-24.72 -166.12,-24.72 -166.12,-25.44 -167.57,-25.44 -167.57,-26.17 -168.3,-26.17 -168.3,-26.9 -169.03,-26.9 -169.03,-29.08 -169.75,-29.08 -169.75,-90.15 -169.03,-90.15 -169.03,-92.33 -168.3,-92.33 -168.3,-93.06 -167.57,-93.06 -167.57,-93.78 -166.12,-93.78 -166.12,-94.51 -163.94,-94.51 -163.94,-95.24 -163.21,-95.24 -163.21,-97.42 -189.38,-97.42 -189.38,-95.24 -188.66,-95.24 -188.66,-94.51 -186.48,-94.51 -186.48,-93.78 -185.02,-93.78 -185.02,-93.06 -184.29,-93.06 -184.29,-91.6 -183.57,-91.6 -183.57,-89.42 -182.84,-89.42 -182.84,-29.81 -183.57,-29.81 -183.57,-27.63 -184.29,-27.63 -184.29,-26.17 -185.75,-26.17 -185.75,-25.44 -186.48,-25.44 -186.48,-24.72 -188.66,-24.72 -188.66,-23.99 -189.38,-23.99 -189.38,-22.54 -163.21,-22.54
  Top Layer region: -1.82,-42.17 -1.09,-42.17 -1.09,-45.07 -0.36,-45.07 -0.36,-47.26 0.36,-47.26 0.36,-49.44 1.09,-49.44 1.09,-51.62 1.82,-51.62 1.82,-55.25 0.36,-55.25 0.36,-54.52 -0.36,-54.52 -0.36,-53.8 -1.09,-53.8 -1.09,-53.07 -1.82,-53.07 -1.82,-52.34 -2.54,-52.34 -2.54,-51.62 -3.27,-51.62 -3.27,-50.89 -4,-50.89 -4,-50.16 -4.73,-50.16 -4.73,-49.44 -5.45,-49.44 -5.45,-48.71 -6.18,-48.71 -6.18,-47.98 -8.36,-47.98 -8.36,-47.26 -11.27,-47.26 -11.27,-46.53 -17.81,-46.53 -17.81,-47.26 -18.54,-47.26 -18.54,-47.98 -19.27,-47.98 -19.27,-90.88 -18.54,-90.88 -18.54,-93.06 -17.81,-93.06 -17.81,-93.78 -16.36,-93.78 -16.36,-94.51 -14.18,-94.51 -14.18,-95.24 -12.72,-95.24 -12.72,-97.42 -37.44,-97.42 -37.44,-95.24 -36.71,-95.24 -36.71,-94.51 -34.53,-94.51 -34.53,-93.78 -33.08,-93.78 -33.08,-93.06 -32.35,-93.06 -32.35,-91.6 -31.62,-91.6 -31.62,-47.26 -33.08,-47.26 -33.08,-46.53 -39.62,-46.53 -39.62,-47.26 -42.53,-47.26 -42.53,-47.98 -43.98,-47.98 -43.98,-48.71 -44.71,-48.71 -44.71,-49.44 -46.16,-49.44 -46.16,-50.16 -46.89,-50.16 -46.89,-50.89 -47.62,-50.89 -47.62,-52.34 -48.35,-52.34 -48.35,-53.07 -49.07,-53.07 -49.07,-53.8 -49.8,-53.8 -49.8,-54.52 -50.53,-54.52 -50.53,-55.25 -51.98,-55.25 -51.98,-54.52 -52.71,-54.52 -52.71,-53.8 -51.98,-53.8 -51.98,-51.62 -51.25,-51.62 -51.25,-49.44 -50.53,-49.44 -50.53,-47.26 -49.8,-47.26 -49.8,-44.35 -49.07,-44.35 -49.07,-42.17 -48.35,-42.17 -48.35,-39.98 -1.82,-39.98
  Top Layer region: 121.05,-42.17 118.86,-42.17 118.86,-42.89 118.14,-42.89 118.14,-43.62 117.41,-43.62 117.41,-44.35 116.68,-44.35 116.68,-45.8 115.96,-45.8 115.96,-82.15 115.23,-82.15 115.23,-85.79 114.5,-85.79 114.5,-87.24 113.78,-87.24 113.78,-88.69 113.05,-88.69 113.05,-90.15 112.32,-90.15 112.32,-90.88 111.59,-90.88 111.59,-92.33 110.87,-92.33 110.87,-93.06 110.14,-93.06 110.14,-93.78 108.69,-93.78 108.69,-94.51 107.96,-94.51 107.96,-95.24 106.51,-95.24 106.51,-95.96 104.32,-95.96 104.32,-96.69 102.14,-96.69 102.14,-97.42 97.78,-97.42 97.78,-98.15 86.15,-98.15 86.15,-97.42 81.79,-97.42 81.79,-96.69 79.61,-96.69 79.61,-95.96 77.43,-95.96 77.43,-95.24 75.97,-95.24 75.97,-94.51 74.52,-94.51 74.52,-93.78 73.79,-93.78 73.79,-93.06 72.34,-93.06 72.34,-92.33 71.61,-92.33 71.61,-91.6 70.88,-91.6 70.88,-90.88 70.16,-90.88 70.16,-90.15 69.43,-90.15 69.43,-88.69 68.7,-88.69 68.7,-87.97 67.97,-87.97 67.97,-86.51 67.25,-86.51 67.25,-84.33 66.52,-84.33 66.52,-47.26 65.79,-47.26 65.79,-45.07 65.07,-45.07 65.07,-43.62 64.34,-43.62 64.34,-42.89 62.89,-42.89 62.89,-42.17 60.7,-42.17 60.7,-39.98 83.97,-39.98 83.97,-42.17 81.79,-42.17 81.79,-42.89 80.33,-42.89 80.33,-43.62 79.61,-43.62 79.61,-45.07 78.88,-45.07 78.88,-47.98 78.15,-47.98 78.15,-79.24 78.88,-79.24 78.88,-82.88 79.61,-82.88 79.61,-85.06 80.33,-85.06 80.33,-86.51 81.06,-86.51 81.06,-87.24 81.79,-87.24 81.79,-87.97 82.51,-87.97 82.51,-88.69 83.97,-88.69 83.97,-89.42 85.42,-89.42 85.42,-90.15 88.33,-90.15 88.33,-90.88 98.51,-90.88 98.51,-90.15 101.42,-90.15 101.42,-89.42 102.87,-89.42 102.87,-88.69 103.6,-88.69 103.6,-87.97 104.32,-87.97 104.32,-87.24 105.05,-87.24 105.05,-86.51 105.78,-86.51 105.78,-85.79 106.51,-85.79 106.51,-83.6 107.23,-83.6 107.23,-80.7 107.96,-80.7 107.96,-47.26 107.23,-47.26 107.23,-45.07 106.51,-45.07 106.51,-43.62 105.78,-43.62 105.78,-42.89 104.32,-42.89 104.32,-42.17 102.14,-42.17 102.14,-39.98 121.05,-39.98
  Top Layer region: 283 vertices and 0 holes, not listed, extent 371.13,-98.15 418.39,-39.26
  Top Layer region: 295 vertices and 0 holes, not listed, extent -98.51,-98.15 -51.25,-39.26
  Top Layer region: 293 vertices and 0 holes, not listed, extent 12,-10.9 59.25,47.98
  Top Layer region: -110.14,45.8 -109.41,45.8 -109.41,44.35 -108.69,44.35 -108.69,42.17 -107.96,42.17 -107.96,39.98 -107.23,39.98 -107.23,37.8 -106.51,37.8 -106.51,36.35 -105.78,36.35 -105.78,33.44 -107.96,33.44 -107.96,34.17 -108.69,34.17 -108.69,34.9 -109.41,34.9 -109.41,35.62 -110.14,35.62 -110.14,36.35 -110.87,36.35 -110.87,37.08 -111.59,37.08 -111.59,37.8 -113.05,37.8 -113.05,38.53 -114.5,38.53 -114.5,39.26 -116.68,39.26 -116.68,39.98 -135.59,39.98 -135.59,39.26 -136.31,39.26 -136.31,38.53 -137.04,38.53 -137.04,23.26 -118.14,23.26 -118.14,23.99 -116.68,23.99 -116.68,24.72 -115.96,24.72 -115.96,26.17 -115.23,26.17 -115.23,27.63 -113.05,27.63 -113.05,11.63 -115.23,11.63 -115.23,13.81 -115.96,13.81 -115.96,14.54 -116.68,14.54 -116.68,15.27 -117.41,15.27 -117.41,15.99 -119.59,15.99 -119.59,16.72 -137.04,16.72 -137.04,-1.45 -136.31,-1.45 -136.31,-2.91 -134.13,-2.91 -134.13,-3.64 -118.86,-3.64 -118.86,-2.91 -113.78,-2.91 -113.78,-2.18 -111.59,-2.18 -111.59,-1.45 -110.14,-1.45 -110.14,-0.73 -109.41,-0.73 -109.41,0 -107.96,0 -107.96,0.73 -107.23,0.73 -107.23,1.45 -106.51,1.45 -106.51,2.18 -105.78,2.18 -105.78,2.91 -105.05,2.91 -105.05,3.64 -104.32,3.64 -104.32,4.36 -103.6,4.36 -103.6,3.64 -102.87,3.64 -102.87,2.18 -103.6,2.18 -103.6,0 -104.32,0 -104.32,-1.45 -105.05,-1.45 -105.05,-3.64 -105.78,-3.64 -105.78,-5.09 -106.51,-5.09 -106.51,-7.27 -107.23,-7.27 -107.23,-8.72 -107.96,-8.72 -107.96,-10.18 -155.21,-10.18 -155.21,-8 -153.03,-8 -153.03,-7.27 -151.58,-7.27 -151.58,-6.54 -150.85,-6.54 -150.85,-5.82 -150.13,-5.82 -150.13,-4.36 -149.4,-4.36 -149.4,41.44 -150.13,41.44 -150.13,42.89 -150.85,42.89 -150.85,43.62 -151.58,43.62 -151.58,44.35 -153.76,44.35 -153.76,45.07 -155.21,45.07 -155.21,47.26 -110.14,47.26
  Top Layer region: 246.82,-41.44 247.54,-41.44 247.54,-42.89 248.27,-42.89 248.27,-45.07 249,-45.07 249,-47.26 249.72,-47.26 249.72,-48.71 250.45,-48.71 250.45,-50.89 251.18,-50.89 251.18,-53.07 250.45,-53.07 250.45,-53.8 249.72,-53.8 249.72,-53.07 249,-53.07 249,-52.34 248.27,-52.34 248.27,-51.62 246.82,-51.62 246.82,-50.89 246.09,-50.89 246.09,-50.16 245.36,-50.16 245.36,-49.44 244.64,-49.44 244.64,-48.71 243.18,-48.71 243.18,-47.98 241,-47.98 241,-47.26 238.09,-47.26 238.09,-46.53 222.83,-46.53 222.83,-47.26 220.64,-47.26 220.64,-48.71 219.92,-48.71 219.92,-63.98 237.37,-63.98 237.37,-63.25 239.55,-63.25 239.55,-62.52 240.27,-62.52 240.27,-61.8 241,-61.8 241,-60.34 241.73,-60.34 241.73,-58.89 243.91,-58.89 243.91,-74.88 241.73,-74.88 241.73,-73.43 241,-73.43 241,-71.97 240.27,-71.97 240.27,-71.25 238.09,-71.25 238.09,-70.52 219.92,-70.52 219.92,-88.69 220.64,-88.69 220.64,-90.15 241.73,-90.15 241.73,-89.42 244.64,-89.42 244.64,-88.69 246.09,-88.69 246.09,-87.97 247.54,-87.97 247.54,-87.24 248.27,-87.24 248.27,-86.51 249,-86.51 249,-85.79 249.72,-85.79 249.72,-85.06 250.45,-85.06 250.45,-84.33 251.18,-84.33 251.18,-83.6 251.91,-83.6 251.91,-82.88 253.36,-82.88 253.36,-83.6 254.09,-83.6 254.09,-85.06 253.36,-85.06 253.36,-86.51 252.63,-86.51 252.63,-88.69 251.91,-88.69 251.91,-90.15 251.18,-90.15 251.18,-92.33 250.45,-92.33 250.45,-93.78 249.72,-93.78 249.72,-95.96 249,-95.96 249,-97.42 201.74,-97.42 201.74,-95.24 203.2,-95.24 203.2,-94.51 204.65,-94.51 204.65,-93.78 206.1,-93.78 206.1,-93.06 206.83,-93.06 206.83,-90.88 207.56,-90.88 207.56,-45.8 206.83,-45.8 206.83,-44.35 206.1,-44.35 206.1,-43.62 205.38,-43.62 205.38,-42.89 203.92,-42.89 203.92,-42.17 201.74,-42.17 201.74,-39.98 246.82,-39.98
  Top Layer region: 249 vertices and 0 holes, not listed, extent 255.54,-98.15 313.7,-39.98
  Top Layer region: 243 vertices and 0 holes, not listed, extent -158.85,-98.15 -100.69,-39.98
  Top Layer region: 193 vertices and 1 holes, not listed, extent 3.27,-98.15 65.79,-39.98
  Top Layer region: 271 vertices and 0 holes, not listed, extent 124.68,-98.15 197.38,-39.98
  Top Layer region: 537 vertices and 1 holes, not listed, extent -104.32,-10.18 14.18,47.26
  Top Layer region: -145.76,62.52 -145.04,62.52 -145.04,60.34 -144.31,60.34 -144.31,58.16 -143.58,58.16 -143.58,55.98 -142.86,55.98 -142.86,53.8 -142.13,53.8 -142.13,51.62 -141.4,51.62 -141.4,50.89 -142.13,50.89 -142.13,50.16 -143.58,50.16 -143.58,51.62 -144.31,51.62 -144.31,52.34 -145.04,52.34 -145.04,53.07 -145.76,53.07 -145.76,53.8 -147.22,53.8 -147.22,54.52 -147.94,54.52 -147.94,55.25 -150.13,55.25 -150.13,55.98 -153.03,55.98 -153.03,56.71 -168.3,56.71 -168.3,55.98 -169.03,55.98 -169.03,54.52 -169.75,54.52 -169.75,-2.91 -169.03,-2.91 -169.03,-5.09 -168.3,-5.09 -168.3,-5.82 -167.57,-5.82 -167.57,-6.54 -166.85,-6.54 -166.85,-7.27 -165.39,-7.27 -165.39,-8 -163.94,-8 -163.94,-10.18 -188.66,-10.18 -188.66,-8 -187.2,-8 -187.2,-7.27 -185.75,-7.27 -185.75,-6.54 -185.02,-6.54 -185.02,-5.82 -184.29,-5.82 -184.29,-5.09 -183.57,-5.09 -183.57,-2.18 -182.84,-2.18 -182.84,53.8 -183.57,53.8 -183.57,55.98 -185.02,55.98 -185.02,56.71 -199.56,56.71 -199.56,55.98 -202.47,55.98 -202.47,55.25 -204.65,55.25 -204.65,54.52 -205.38,54.52 -205.38,53.8 -206.83,53.8 -206.83,53.07 -207.56,53.07 -207.56,52.34 -208.29,52.34 -208.29,51.62 -209.01,51.62 -209.01,50.89 -209.74,50.89 -209.74,50.16 -210.47,50.16 -210.47,50.89 -211.19,50.89 -211.19,53.07 -210.47,53.07 -210.47,54.52 -209.74,54.52 -209.74,56.71 -209.01,56.71 -209.01,58.89 -208.29,58.89 -208.29,61.07 -207.56,61.07 -207.56,63.25 -206.83,63.25 -206.83,64.7 -145.76,64.7
  Top Layer region: -285.35,85.79 -286.07,85.79 -286.07,82.15 -286.8,82.15 -286.8,78.52 -287.53,78.52 -287.53,74.88 -288.26,74.88 -288.26,71.97 -305.7,71.97 -305.7,73.43 -304.98,73.43 -304.98,77.06 -304.25,77.06 -304.25,80.7 -303.52,80.7 -303.52,84.33 -302.8,84.33 -302.8,87.97 -302.07,87.97 -302.07,88.69 -285.35,88.69
  Top Layer region: -289.71,63.25 -290.44,63.25 -290.44,59.61 -291.16,59.61 -291.16,55.98 -291.89,55.98 -291.89,52.34 -292.62,52.34 -292.62,48.71 -293.34,48.71 -293.34,45.07 -294.07,45.07 -294.07,41.44 -294.8,41.44 -294.8,37.8 -295.53,37.8 -295.53,34.17 -296.25,34.17 -296.25,30.53 -296.98,30.53 -296.98,26.9 -297.71,26.9 -297.71,23.26 -298.43,23.26 -298.43,19.63 -299.16,19.63 -299.16,15.99 -299.89,15.99 -299.89,12.36 -300.61,12.36 -300.61,8.72 -301.34,8.72 -301.34,5.09 -302.07,5.09 -302.07,1.45 -302.8,1.45 -302.8,-2.18 -303.52,-2.18 -303.52,-5.82 -304.25,-5.82 -304.25,-9.45 -321.7,-9.45 -321.7,-7.27 -320.97,-7.27 -320.97,-3.64 -320.24,-3.64 -320.24,0 -319.52,0 -319.52,3.64 -318.79,3.64 -318.79,7.27 -318.06,7.27 -318.06,10.9 -317.34,10.9 -317.34,14.54 -316.61,14.54 -316.61,18.18 -315.88,18.18 -315.88,21.81 -315.15,21.81 -315.15,25.44 -314.43,25.44 -314.43,29.08 -313.7,29.08 -313.7,32.72 -312.97,32.72 -312.97,36.35 -312.25,36.35 -312.25,39.98 -311.52,39.98 -311.52,43.62 -310.79,43.62 -310.79,47.26 -310.07,47.26 -310.07,50.89 -309.34,50.89 -309.34,54.52 -308.61,54.52 -308.61,58.16 -307.88,58.16 -307.88,61.8 -307.16,61.8 -307.16,64.7 -289.71,64.7
  Top Layer region: 519 vertices and 0 holes, not listed, extent -418.39,-77.79 -237.37,98.15
TO-220AB [mil] "Copied from Altium's version of TO3B"
  rect 76x118.11 hole 50: 1(-100,0)
  oval 76x118.11 hole 50: 2(0,0) 3(100,0)
  silkscreen extent -225,-73 225,130, body extent -221,-59 221,126, height 765
TP-040_RND [mil]
  round 70 / inner round 62 / far side round 62 hole 40: 1(0,0)
YXJ_1000x2000 [mm] "RUBYCON"
  rect 1.7x1.7 hole 0.914: 1(-2.5,0)
  round 1.7 hole 0.914: 2(2.5,0)
  silkscreen extent -5.3,-5.3 5.3,5.3, body extent -5.21,-5.24 5.24,5.24, height 22.01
